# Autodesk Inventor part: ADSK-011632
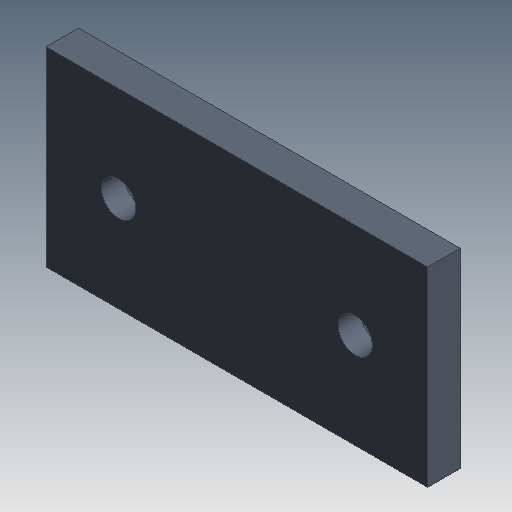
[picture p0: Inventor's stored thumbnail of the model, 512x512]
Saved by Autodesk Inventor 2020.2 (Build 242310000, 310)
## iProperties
Created: 2000-02
Part Number: ADSK-011632
Material: Pearson Nylatron
Document SubType Name: Modeling
Description: PLT-02,SN,AX,03,040,020,WW,PAD,SIDE GUIDE ASSY
Designer: sspink
Density: 1.13867 g/cm^3
Appearance: Nylatron
Mass: 54.3806 g
Surface Area: 129.51 cm^2
Volume: 47.758 cm^3
Control State: 0
Checked Out: False
Master: False
Shininess: 10.0
Length Units: 11269
Angle Units: 11279
Time Units: 11290
Mass Units: 11283
Length Display Precision: 3
Angle Display Precision: 2
Compacted: True
Cutlength: 8 SI  (2.0 X 4.0)
Material Desc: SHEET,NYLATRON,0.375
Material_Number: A088786
Dimensions: 50x10x100 mm
Mass: 0,054 kg
VLT_Material: Pearson Nylatron
Density: 1.13867
Volumn: 45.865799413712445
Area: 130.99447146076915
PropertySet Name: Model Information
Title: PLT-02,PAD,SIDE GUIDE ASSY
Author: sspink
Revision Number: -
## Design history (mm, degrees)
node "Solide1"
  node "Extrusion1" dims "d2" = 10, "d3" = 0
  node "Hole1" dims "d6" = 9, "d7" = 17.3, "d8" = 6.35, "d9" = 90 deg, "d10" = 19.05, "d11" = 118 deg, "d22" = 6
  node "Chamfer1" dims "d18" = 1.5, "d19" = 1.5, "d20" = 45 deg
sketch "Sketch1"
  geometry: L1 (-50, -25)-(50, -25); L2 (50, -25)-(50, 25); L3 (50, 25)-(-50, 25); L4 (-50, 25)-(-50, -25); 3 further points
  constraints: 8 end point, 2 midpoint, 2 parallel, 1 horizontal, 1 horizontal alignment, 1 perpendicular, 1 vertical alignment
  dimensions: "d0" = 100 distance between parallel lines of L2 L4; "d1" = 50 distance between parallel lines of L3 L1
sketch "Sketch2"
  geometry: L1 (-31, 0)-(31, 0); 1 further point
  constraints: 2 end point, 1 horizontal, 1 midpoint
  dimensions: "d21" = 62 distance of L1.end L1.start
node "Corps solides"
node "Corps surfaciques"
